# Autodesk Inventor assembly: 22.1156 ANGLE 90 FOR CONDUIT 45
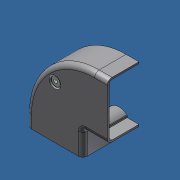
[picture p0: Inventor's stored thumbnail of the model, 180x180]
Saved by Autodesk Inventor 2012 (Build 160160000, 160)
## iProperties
Created: 2014-05
Part Number: 22.1156 ANGLE 90 FOR CONDUIT 45
Document SubType Name: Assembly
Designer: Admin
Author: Admin
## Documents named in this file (4)
- C:\Andys Backup Data\ANDY'S INVENTOR\INVENTOR LIBRARIES\PARTS LIBRARY\ELECTRICAL INSTALLATION\22.1156 ANGLE 90 FOR CONDUIT 45.iam
- C:\Andys Backup Data\ANDY'S INVENTOR\INVENTOR LIBRARIES\PARTS LIBRARY\ELECTRICAL INSTALLATION\SUBCOMPONENTS\22.1156 ANGLE 90 CONDUIT 45.ipt
- C:\Andys Backup Data\ANDY'S INVENTOR\INVENTOR LIBRARIES\PARTS LIBRARY\FASTENING ELEMENTS\SCREWS CAP\21.2195 M5X35.ipt
- C:\Andys Backup Data\ANDY'S INVENTOR\INVENTOR LIBRARIES\PARTS LIBRARY\FASTENING ELEMENTS\NUTS\21.1320 M5 SQUARE NUT.ipt
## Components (3 placed, 3 different names)
1. 22.1156 ANGLE 90 CONDUIT 45:1 — Insert:1, Mate:2, Angle:1
2. 21.1237 M5 x 30:1 — Insert:1, Mate:1
3. 21.1320 M5 SQUARE NUT:1 — Mate:1, Mate:2, Angle:1
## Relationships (4: Mate 2, Insert 1, Angle 1)
- Insert:1: 22.1156 ANGLE 90 CONDUIT 45:1 ↔ 21.1237 M5 x 30:1
- Mate:1: 21.1237 M5 x 30:1 ↔ 21.1320 M5 SQUARE NUT:1
- Mate:2: 22.1156 ANGLE 90 CONDUIT 45:1 ↔ 21.1320 M5 SQUARE NUT:1
- Angle:1: 22.1156 ANGLE 90 CONDUIT 45:1 ↔ 21.1320 M5 SQUARE NUT:1
